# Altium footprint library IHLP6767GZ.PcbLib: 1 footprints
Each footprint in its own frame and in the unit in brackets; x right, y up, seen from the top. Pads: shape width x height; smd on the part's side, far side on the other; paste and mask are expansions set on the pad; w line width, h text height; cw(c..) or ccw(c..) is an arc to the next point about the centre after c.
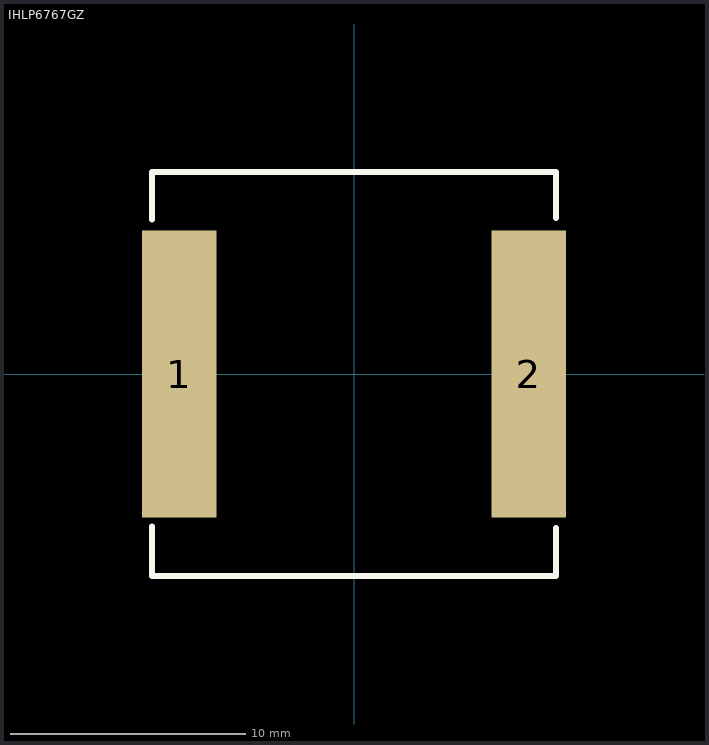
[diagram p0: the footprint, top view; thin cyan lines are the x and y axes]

## IHLP6767GZ [mm] "IHLP6767GZ VISHAY DALE INDUCTOR"
height 7
pads (2):
  rect 3.175x12.19 smd: 1(-7.428,0) 2(7.428,0)
Top Overlay:
  lines w0.254: -8.575,-6.475 -8.575,-8.575 8.575,-8.575 8.575,-6.55 ; -8.575,6.575 -8.575,8.575 8.575,8.575 8.575,6.625
M5 Assembly Top:
  text ".Designator" at 0,0 h1.02
3D body: height 7, standoff 0, extent -8.625,-8.6 8.675,8.675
